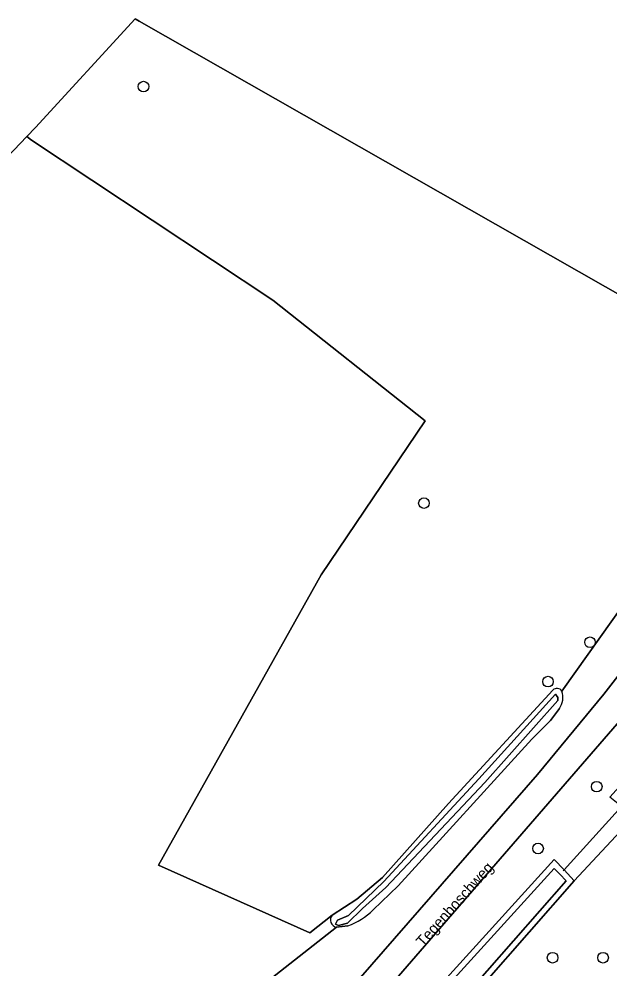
# Model space of a CAD drawing. Extents: x 156502 to 159075, y 384229 to 386100.
# Drawn here: x 156919 to 156973.3, y 385540.6 to 385627.9 of the extents above; entities that cross this region are included whole.
import ezdxf

# ---------------------------------------------------------------- set-up
doc = ezdxf.new("R2010")
doc.units = 0
for name, color, linetype in [('IMGEO_Boom', 7, 'Continuous'), ('IMGEO_Duiker', 7, 'Continuous'), ('IMGEO_Grasland_agrarisch', 7, 'Continuous'), ('IMGEO_Greppel_droge_sloot', 7, 'Continuous'), ('IMGEO_Groenvoorziening', 7, 'Continuous'), ('IMGEO_Loofbos', 7, 'Continuous'), ('IMGEO_Oever', 7, 'Continuous'), ('IMGEO_Openbare_ruimte_label', 7, 'Continuous'), ('IMGEO_Rijbaan_lokaal_gesloten', 7, 'Continuous'), ('IMGEO_Waterloop', 7, 'Continuous')]:
    doc.layers.add(name, color=color, linetype=linetype)

msp = doc.modelspace()

# ---------------------------------------------------------------- linework, layer by layer
at = {"layer": 'IMGEO_Boom'}
for centre in [(156930.443, 385621.659), (156956.272, 385583.334), (156971.561, 385570.53), (156967.693, 385566.907), (156972.178, 385557.243), (156966.775, 385551.549), (156968.114, 385541.502), (156972.762, 385541.502)]:
    msp.add_circle(centre, 0.489, dxfattribs=at)
at = {"layer": 'IMGEO_Duiker'}
msp.add_lwpolyline([(156974.628, 385555.59), (156974.464, 385555.409), (156969.174, 385549.58), (156969.1, 385549.498)], dxfattribs=at)
at = {"layer": 'IMGEO_Grasland_agrarisch'}
msp.add_lwpolyline([(156911.288, 385608.272), (156919.717, 385617.07), (156920.513, 385617.902), (156929.681, 385627.879), (156930.043, 385627.665), (156988.164, 385594.573), (156988.529, 385595.877), (156997.516, 385605.96), (157000, 385609.231)], dxfattribs=at)
at = {"layer": 'IMGEO_Greppel_droge_sloot'}
msp.add_lwpolyline([(156957.245, 385534.774), (156969.359, 385548.574), (156968.769, 385549.195), (156968.263, 385549.727), (156953.85, 385533.849), (156962.21, 385528.959), (156977.132, 385519.654), (157000.293, 385505.706), (157008.622, 385500.476), (157087.914, 385452.803), (157130.235, 385427.094), (157139.294, 385422.402)], dxfattribs=at)
at = {"layer": 'IMGEO_Groenvoorziening'}
for points in [[(156968.97, 385566.029), (156988.883, 385593.995), (156988.164, 385594.573), (156930.043, 385627.665), (156929.681, 385627.879), (156920.513, 385617.902), (156919.717, 385617.07), (156920.147, 385616.718), (156942.349, 385602.002), (156956.375, 385590.896), (156946.815, 385576.729), (156931.815, 385550.024), (156945.757, 385543.789), (156947.815, 385545.428), (156950.099, 385546.9), (156952.447, 385548.888), (156958.521, 385555.7), (156968.134, 385566.126)], [(157000, 385606.133), (156999.018, 385604.875), (156989.883, 385593.806), (156989.578, 385593.437), (156988.883, 385593.995), (156968.97, 385566.029)], [(156914.089, 385492.498), (156921.866, 385504.388), (156935.737, 385522.672), (156946.428, 385535.09), (156947.082, 385535.84), (156966.71, 385558.349), (156972.838, 385565.742), (156981.157, 385576.439), (156979.885, 385577.425), (156979.51, 385577.715), (156991.85, 385592.399), (156993.475, 385594.437), (156997.186, 385598.893)], [(156988.214, 385577.439), (156984.873, 385573.394), (156983.822, 385574.267), (156948.741, 385533.816), (156937.699, 385521.084)], [(156943.317, 385520.772), (156952.566, 385531.025), (156952.973, 385533.714), (156968.254, 385550.548), (156969.174, 385549.58), (156970.115, 385548.589), (156975.634, 385554.485), (156974.464, 385555.409), (156973.372, 385556.271), (156987.681, 385572.1), (156989.039, 385571.117), (156989.983, 385570.433), (156991.332, 385572.02), (156994.071, 385576.896)], [(157059.483, 385535.302), (156991.332, 385572.02), (156989.983, 385570.433), (156975.634, 385554.485), (156970.115, 385548.589), (156957.679, 385534.422)], [(156968.741, 385564.425), (156967.929, 385563.341), (156966.191, 385561.602), (156953.889, 385548.102), (156951.588, 385545.901)], [(156949.267, 385544.438), (156948.225, 385544.3), (156942.206, 385539.594)]]:
    msp.add_lwpolyline(points, dxfattribs=at)
for centre, radius, start, end in [((156968.513, 385565.742), 0.54, 32.13754, 134.62574), ((156967.271, 385565.453), 1.794, 325.0223, 18.7275), ((156947.266, 385550.186), 6.086, 289.1983, 315.25077)]:
    msp.add_arc(centre, radius, start, end, dxfattribs=at)
at = {"layer": 'IMGEO_Loofbos'}
for points in [[(156946.815, 385576.729), (156956.375, 385590.896), (156942.349, 385602.002), (156920.147, 385616.718), (156919.717, 385617.07), (156911.288, 385608.272)], [(156947.815, 385545.428), (156945.757, 385543.789), (156931.815, 385550.024), (156946.815, 385576.729)], [(156942.206, 385539.594), (156948.225, 385544.3)]]:
    msp.add_lwpolyline(points, dxfattribs=at)
msp.add_arc((156948.348, 385544.983), 0.694, 140.14533, 259.80457, dxfattribs=at)
at = {"layer": 'IMGEO_Oever'}
for points in [[(156968.134, 385566.126), (156958.521, 385555.7), (156952.447, 385548.888), (156950.099, 385546.9), (156947.815, 385545.428)], [(156951.588, 385545.901), (156953.889, 385548.102), (156966.191, 385561.602), (156967.929, 385563.341), (156968.741, 385564.425)], [(156969.174, 385549.58), (156968.254, 385550.548), (156952.973, 385533.714), (156961.921, 385528.481), (156976.84, 385519.178), (157000, 385505.23), (157008.33, 385500), (157087.625, 385452.325), (157131.785, 385425.499), (157136.208, 385423.179), (157137.543, 385422.417), (157138.901, 385421.726), (157140.311, 385421.153)], [(157139.294, 385422.402), (157130.235, 385427.094), (157087.914, 385452.803), (157008.622, 385500.476), (157000.293, 385505.706), (156977.132, 385519.654), (156962.21, 385528.959), (156953.85, 385533.849), (156968.263, 385549.727), (156968.769, 385549.195), (156969.359, 385548.574), (156957.245, 385534.774)], [(156957.679, 385534.422), (156970.115, 385548.589), (156969.174, 385549.58)], [(156948.225, 385544.3), (156949.267, 385544.438)]]:
    msp.add_lwpolyline(points, dxfattribs=at)
msp.add_lwpolyline([(156968.391, 385565.738), (156968.592, 385565.457), (156968.6, 385565.161), (156961.884, 385557.625), (156952.748, 385547.977), (156950.61, 385546.026), (156949.233, 385544.69), (156948.408, 385544.48), (156948.111, 385544.602), (156948.323, 385544.955), (156949.319, 385545.4), (156952.587, 385548.527), (156961.325, 385557.953)], close=True, dxfattribs=at)
for centre, radius, start, end in [((156968.513, 385565.742), 0.54, 32.13754, 134.62574), ((156967.271, 385565.453), 1.794, 325.0223, 18.7275), ((156948.348, 385544.983), 0.694, 140.14533, 259.80457), ((156947.266, 385550.186), 6.086, 289.1983, 315.25077)]:
    msp.add_arc(centre, radius, start, end, dxfattribs=at)
at = {"layer": 'IMGEO_Rijbaan_lokaal_gesloten'}
for points in [[(156983.822, 385574.267), (156981.157, 385576.439), (156972.838, 385565.742), (156966.71, 385558.349), (156947.082, 385535.84), (156946.428, 385535.09), (156935.737, 385522.672), (156921.866, 385504.388), (156914.089, 385492.498), (156913.487, 385486.961), (156923.928, 385502.931)], [(156937.699, 385521.084), (156948.741, 385533.816), (156983.822, 385574.267)]]:
    msp.add_lwpolyline(points, dxfattribs=at)
at = {"layer": 'IMGEO_Waterloop'}
msp.add_lwpolyline([(156968.391, 385565.738), (156961.325, 385557.953), (156952.587, 385548.527), (156949.319, 385545.4), (156948.323, 385544.955), (156948.111, 385544.602), (156948.408, 385544.48), (156949.233, 385544.69), (156950.61, 385546.026), (156952.748, 385547.977), (156961.884, 385557.625), (156968.6, 385565.161), (156968.592, 385565.457)], close=True, dxfattribs=at)

# ---------------------------------------------------------------- texts
at = {"layer": 'IMGEO_Openbare_ruimte_label'}
msp.add_text('Tegenboschweg', height=1, rotation=48.16185, dxfattribs=at).set_placement((156956.192, 385542.434))

doc.saveas('drawing.dxf')
